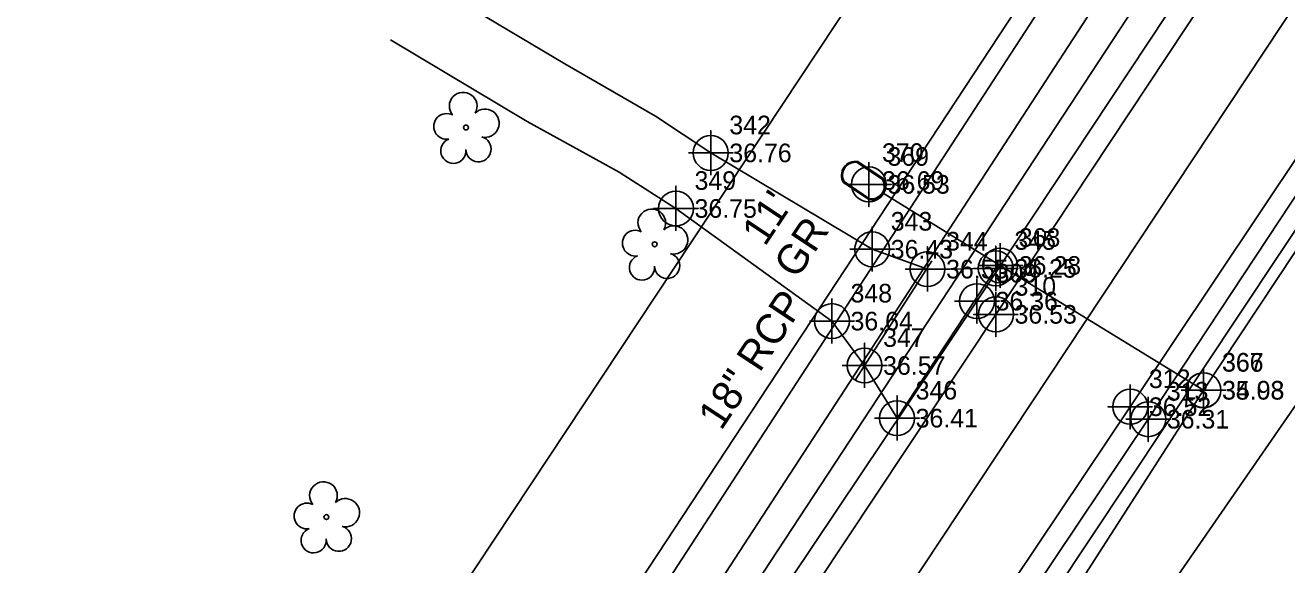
# Model space of a CAD drawing. Extents: x 2603627 to 2605187, y 896619 to 899063.
# Drawn here: x 2604617.7 to 2604787, y 898454.7 to 898527.2 of the extents above; entities that cross this region are included whole.
import ezdxf

# ---------------------------------------------------------------- set-up
doc = ezdxf.new("R2010")
doc.units = 0
for name, color, linetype in [('CTL Supplemental Horizontal and Vertical CELL', 7, 'Continuous'), ('Exist Horizontal Alignment', 7, 'Continuous'), ('Exist Horizontal Baseline Alignment', 7, 'Continuous'), ('Exist Right of Way Line', 7, 'Continuous'), ('Exist Roads EOP', 7, 'Continuous'), ('Exist Roads EOP Cogo Elevation', 7, 'Continuous'), ('Exist Roads EOP Cogo Number', 7, 'Continuous'), ('Exist Roads EOP Cogo Point CELL', 7, 'Continuous'), ('Exist Roads EOT', 7, 'Continuous'), ('Exist Roads EOT Cogo Elevation', 7, 'Continuous'), ('Exist Roads EOT Cogo Number', 7, 'Continuous'), ('Exist Roads EOT Cogo Point CELL', 7, 'Continuous'), ('Exist Roads Soil', 7, 'Continuous'), ('Exist Roads Soil Cogo Elevation', 7, 'Continuous'), ('Exist Roads Soil Cogo Number', 7, 'Continuous'), ('Exist Roads Soil Cogo Point CELL', 7, 'Continuous'), ('Exist Roads Soil Text', 7, 'Continuous'), ('Exist Structure Minor Pipes RCP 18 Inch', 7, 'Continuous'), ('Exist Structure Minor Pipes RCP 18 Inch Text', 7, 'Continuous'), ('Exist Utilities Telephone UG Cable SUE LOS C', 7, 'Continuous'), ('Exist Utilities Telephone UG FO SUE LOS C', 7, 'Continuous'), ('Exist Utilities Water Meter CELL', 7, 'Continuous'), ('Exist Utilities Water Meter Cogo Elevation', 7, 'Continuous'), ('Exist Utilities Water Meter Cogo Number', 7, 'Continuous'), ('Exist Utilities Water UG Line SUE LOS B', 7, 'Continuous'), ('Exist Utilities Water UG Line SUE LOS B Cogo Elevation', 7, 'Continuous'), ('Exist Utilities Water UG Line SUE LOS B Cogo Number', 7, 'Continuous'), ('Exist Utilities Water UG Line SUE LOS B Cogo Point CELL', 7, 'Continuous'), ('Exist Vegetation Tree CELL', 7, 'Continuous')]:
    doc.layers.add(name, color=color, linetype=linetype)

# ---------------------------------------------------------------- blocks, each defined once
blk = doc.blocks.new('EXIST ROADS EOP COGO POINT')
at = {"layer": 'Exist Roads EOP Cogo Point CELL'}
blk.add_lwpolyline([(0, 0.06), (0, -0.06), (0, 0), (0.06, 0), (-0.06, 0)], dxfattribs=at)
blk.add_circle((0, 0), 0.0469, dxfattribs=at)
blk = doc.blocks.new('EXIST ROADS EOT COGO POINT')
at = {"layer": 'Exist Roads EOT Cogo Point CELL'}
blk.add_lwpolyline([(0, 0.06), (0, -0.06), (0, 0), (-0.06, 0), (0.06, 0)], dxfattribs=at)
blk.add_circle((0, 0), 0.0469, dxfattribs=at)
blk = doc.blocks.new('EXIST ROADS SOIL COGO POINT')
at = {"layer": 'Exist Roads Soil Cogo Point CELL'}
blk.add_lwpolyline([(0, -0.06), (0, 0.06), (0, 0), (0.06, 0), (-0.06, 0)], dxfattribs=at)
blk.add_circle((0, 0), 0.0469, dxfattribs=at)
blk = doc.blocks.new('EXIST UTILITIES WATER UG LINE SUE LOS B COGO POINT')
at = {"layer": 'Exist Utilities Water UG Line SUE LOS B Cogo Point CELL'}
blk.add_lwpolyline([(0, 0.06), (0, -0.06), (0, 0), (0.06, 0), (-0.06, 0)], dxfattribs=at)
blk.add_circle((0, 0), 0.0469, dxfattribs=at)
blk = doc.blocks.new('EXIST UTILITIES WATER METER')
at = {"layer": 'Exist Utilities Water Meter CELL'}
blk.add_line((0, 0), (0, 0), dxfattribs=at)
for points in [[(-0.0408, 0.034), (0.0408, 0.034)], [(-0.0408, 0.0312), (0.0408, 0.0312)], [(0.0408, -0.0312), (-0.0413, -0.0312)], [(0.0408, -0.034), (-0.0413, -0.034)]]:
    blk.add_lwpolyline(points, dxfattribs=at)
for centre, radius, start, end in [((-0.0261, -0.0001), 0.0371, 113.178, 245.9794), ((0.0259, 0), 0.0371, 293.6483, 66.3084), ((-0.0259, -0.0001), 0.0347, 115.3009, 243.7824), ((0.0261, 0), 0.0345, 295.1272, 64.8728)]:
    blk.add_arc(centre, radius, start, end, dxfattribs=at)
blk = doc.blocks.new('CTL SUPPLEMENTAL HORIZONTAL AND VERTICAL')
at = {"layer": 'CTL Supplemental Horizontal and Vertical CELL'}
blk.add_line((0, 0), (0, 0), dxfattribs=at)
blk.add_lwpolyline([(-0.1043, 0.0004), (0.0005, 0.1052), (0.1055, 0.0002), (0.0007, -0.1047)], close=True, dxfattribs=at)

msp = doc.modelspace()

# ---------------------------------------------------------------- linework, layer by layer
at = {"layer": 'Exist Horizontal Alignment'}
msp.add_line((2604681.44, 898368.79), (2605041.11, 898911.74), dxfattribs=at)
at = {"layer": 'Exist Horizontal Baseline Alignment'}
msp.add_line((2604544.96, 898124.44), (2604793.6, 898483.9), dxfattribs=at)
at = {"layer": 'Exist Right of Way Line'}
msp.add_line((2604639.76, 898396.41), (2604999.42, 898939.36), dxfattribs=at)
at = {"layer": 'Exist Roads EOP'}
for points in [[(2604577.96, 898237.27), (2604606.45, 898281.24), (2604633.89, 898322.5), (2604662.45, 898365.47), (2604690.62, 898408.06), (2604717.29, 898448.09), (2604745.46, 898490.11), (2604773.6, 898532.6), (2604800.88, 898573.95), (2604828.34, 898615.46), (2604855.1, 898656.15), (2604883.53, 898699.09), (2604911.29, 898740.95), (2604939.38, 898783.41), (2604966.33, 898824.04), (2604993.38, 898865.27), (2605022.2, 898908.38), (2605029.46, 898919.46)], [(2604713.86, 898392.44), (2604740.28, 898432.25), (2604768.45, 898474.26), (2604797.27, 898517.92), (2604823.93, 898558.47), (2604851.31, 898599.84), (2604878.52, 898641.09), (2604906.84, 898683.65), (2604934.68, 898725.71), (2604962.63, 898767.92), (2604989.32, 898808.49), (2605016.42, 898849.59), (2605045.34, 898893.33), (2605052.55, 898904.16)]]:
    msp.add_lwpolyline(points, dxfattribs=at)
at = {"layer": 'Exist Roads EOT'}
for points in [[(2604580.65, 898235.67), (2604609.23, 898279.3), (2604636.66, 898320.72), (2604665.18, 898363.91), (2604693.37, 898406.36), (2604719.95, 898446.05), (2604748, 898488.34), (2604776.15, 898530.84), (2604803.5, 898572.3), (2604830.95, 898613.91), (2604857.58, 898654.47), (2604886.02, 898697.38), (2604913.86, 898739.33), (2604942.03, 898781.72), (2604969.06, 898822.38), (2604996.07, 898863.44), (2605024.73, 898906.73), (2605032, 898917.78)], [(2604598.04, 898223.4), (2604627.23, 898267.23), (2604654.64, 898308.57), (2604683.28, 898352.01), (2604711.27, 898394.14), (2604737.98, 898434.05), (2604766.04, 898475.94), (2604794.96, 898519.26), (2604821.61, 898559.82), (2604848.89, 898601.4), (2604876.12, 898642.73), (2604904.4, 898685.35), (2604932.33, 898727.23), (2604960.29, 898769.49), (2604987.32, 898810.19), (2605014.12, 898850.95), (2605043.08, 898894.89), (2605050.2, 898905.72)]]:
    msp.add_lwpolyline(points, dxfattribs=at)
at = {"layer": 'Exist Roads Soil'}
for p, q in [((2604709.71, 898510.01), (2604702.3, 898514.93)), ((2604705.04, 898502.55), (2604697.44, 898507.43))]:
    msp.add_line(p, q, dxfattribs=at)
for points in [[(2604702.3, 898514.93), (2604690.11, 898521.97), (2604671.82, 898532.91)], [(2604697.44, 898507.43), (2604685.07, 898514.22), (2604666.71, 898525.2)], [(2604709.71, 898510.01), (2604731.38, 898497.08), (2604738.81, 898494.41), (2604747.98, 898494.51), (2604734.72, 898474.4), (2604730.36, 898481.47), (2604725.98, 898487.43), (2604705.04, 898502.55)]]:
    msp.add_lwpolyline(points, dxfattribs=at)
at = {"layer": 'Exist Structure Minor Pipes RCP 18 Inch'}
msp.add_line((2604729.12, 898479.5), (2604739.41, 898495.51), dxfattribs=at)
at = {"layer": 'Exist Utilities Telephone UG Cable SUE LOS C'}
for p, q in [((2604658.71, 898389.49), (2604852.96, 898684.66)), ((2604753.32, 898447.21), (2604850.74, 898593.69)), ((2604580.04, 898245.37), (2604795.48, 898573.63))]:
    msp.add_line(p, q, dxfattribs=at)
at = {"layer": 'Exist Utilities Telephone UG FO SUE LOS C'}
for p, q in [((2604671.2, 898402.26), (2605014.35, 898929.48)), ((2604676.14, 898398.98), (2605019.3, 898926.2))]:
    msp.add_line(p, q, dxfattribs=at)
at = {"layer": 'Exist Utilities Water UG Line SUE LOS B'}
for points in [[(2604590.41, 898183.07), (2604608.13, 898210.78), (2604631.33, 898247.72), (2604631.98, 898248.77), (2604637.93, 898260.9), (2604650.01, 898281.75), (2604670.13, 898312.66), (2604706.14, 898370.49), (2604744.2, 898428.79), (2604775.85, 898478.14), (2604817.62, 898541.22), (2604844.76, 898580.18), (2604876.2, 898627.22), (2604907.55, 898675.15), (2604931.69, 898711.47), (2604963.51, 898758.63), (2604991.08, 898800.9), (2605022.23, 898847.26), (2605044.13, 898880.13), (2605057.71, 898900.74)], [(2604775.86, 898478.17), (2604748.57, 898494.9), (2604732.86, 898504.6)]]:
    msp.add_lwpolyline(points, dxfattribs=at)
at = {"layer": 'Exist Vegetation Tree CELL'}
for p, q in [((2604676.86, 898513.42), (2604676.86, 898513.42)), ((2604702.18, 898497.75), (2604702.18, 898497.75)), ((2604658.11, 898461.12), (2604658.11, 898461.12))]:
    msp.add_line(p, q, dxfattribs=at)
for centre in [(2604676.86, 898513.42), (2604702.18, 898497.75), (2604658.11, 898461.12)]:
    msp.add_circle(centre, 0.326, dxfattribs=at)
for centre, radius, start, end in [((2604676.48, 898516.29), 1.86, 330.1651, 219.7134), ((2604674.26, 898513.57), 1.73, 62.6636, 279.3457), ((2604679.41, 898514), 1.9, 257.1011, 134.1999), ((2604675.16, 898510.29), 1.69, 111.5671, 6.231), ((2604678.53, 898510.52), 1.7, 181.2822, 74.56), ((2604701.8, 898500.62), 1.86, 330.1651, 219.7134), ((2604699.58, 898497.9), 1.73, 62.6636, 279.3457), ((2604704.73, 898498.33), 1.9, 257.1011, 134.1999), ((2604703.86, 898494.85), 1.7, 181.2822, 74.56), ((2604700.48, 898494.62), 1.69, 111.5671, 6.231), ((2604657.72, 898463.99), 1.86, 330.1651, 219.7134), ((2604655.5, 898461.27), 1.73, 62.6636, 279.3457), ((2604660.66, 898461.71), 1.9, 257.1011, 134.1999), ((2604656.4, 898458), 1.69, 111.5671, 6.231), ((2604659.78, 898458.22), 1.7, 181.2822, 74.56)]:
    msp.add_arc(centre, radius, start, end, dxfattribs=at)

# ---------------------------------------------------------------- block references
at = {"layer": 'CTL Supplemental Horizontal and Vertical CELL', "xscale": 50, "yscale": 49.99999999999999, "rotation": 57.44453205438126}
msp.add_blockref('CTL SUPPLEMENTAL HORIZONTAL AND VERTICAL', (2604793.6, 898483.9), dxfattribs=at)
at = {"layer": 'Exist Roads EOP Cogo Point CELL', "xscale": 50, "yscale": 50}
for p in [(2604745.46, 898490.11), (2604768.45, 898474.26)]:
    msp.add_blockref('EXIST ROADS EOP COGO POINT', p, dxfattribs=at)
at = {"layer": 'Exist Roads EOT Cogo Point CELL', "xscale": 50, "yscale": 50}
for p in [(2604748, 898488.34), (2604766.04, 898475.94)]:
    msp.add_blockref('EXIST ROADS EOT COGO POINT', p, dxfattribs=at)
at = {"layer": 'Exist Roads Soil Cogo Point CELL', "xscale": 50, "yscale": 50}
for p in [(2604709.71, 898510.01), (2604705.04, 898502.55), (2604731.38, 898497.08), (2604738.81, 898494.41), (2604747.98, 898494.51), (2604725.98, 898487.43), (2604730.36, 898481.47), (2604734.72, 898474.4)]:
    msp.add_blockref('EXIST ROADS SOIL COGO POINT', p, dxfattribs=at)
at = {"layer": 'Exist Utilities Water Meter CELL', "xscale": 50, "yscale": 50, "rotation": -33.955010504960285}
msp.add_blockref('EXIST UTILITIES WATER METER', (2604730.21, 898506.3), dxfattribs=at)
at = {"layer": 'Exist Utilities Water UG Line SUE LOS B Cogo Point CELL', "xscale": 50, "yscale": 50}
for p in [(2604730.94, 898505.79), (2604748.57, 898494.9), (2604775.85, 898478.14), (2604775.87, 898478.16)]:
    msp.add_blockref('EXIST UTILITIES WATER UG LINE SUE LOS B COGO POINT', p, dxfattribs=at)

# ---------------------------------------------------------------- texts
at = {"layer": 'Exist Roads EOP Cogo Elevation'}
for s, p in [('36.36', (2604747.96, 898488.86)), ('36.31', (2604770.95, 898473.01))]:
    msp.add_text(s, height=2.5, dxfattribs=at).set_placement(p)
at = {"layer": 'Exist Roads EOP Cogo Number'}
for s, p in [('309', (2604747.96, 898492.61)), ('313', (2604770.95, 898476.76))]:
    msp.add_text(s, height=2.5, dxfattribs=at).set_placement(p)
at = {"layer": 'Exist Roads EOT Cogo Elevation'}
for s, p in [('36.53', (2604750.5, 898487.09)), ('36.52', (2604768.54, 898474.69))]:
    msp.add_text(s, height=2.5, dxfattribs=at).set_placement(p)
at = {"layer": 'Exist Roads EOT Cogo Number'}
for s, p in [('310', (2604750.5, 898490.84)), ('312', (2604768.54, 898478.44))]:
    msp.add_text(s, height=2.5, dxfattribs=at).set_placement(p)
at = {"layer": 'Exist Roads Soil Cogo Elevation'}
for s, p in [('36.76', (2604712.21, 898508.76)), ('36.75', (2604707.54, 898501.3)), ('36.43', (2604733.88, 898495.83)), ('36.55', (2604741.31, 898493.16)), ('36.25', (2604750.48, 898493.26)), ('36.64', (2604728.48, 898486.18)), ('36.57', (2604732.86, 898480.22)), ('36.41', (2604737.22, 898473.15))]:
    msp.add_text(s, height=2.5, dxfattribs=at).set_placement(p)
at = {"layer": 'Exist Roads Soil Cogo Number'}
for s, p in [('342', (2604712.21, 898512.51)), ('349', (2604707.54, 898505.05)), ('343', (2604733.88, 898499.58)), ('344', (2604741.31, 898496.91)), ('345', (2604750.48, 898497.01)), ('348', (2604728.48, 898489.93)), ('347', (2604732.86, 898483.97)), ('346', (2604737.22, 898476.9))]:
    msp.add_text(s, height=2.5, dxfattribs=at).set_placement(p)
at = {"layer": 'Exist Roads Soil Text'}
for s, p in [("11' ", (2604716.98, 898497.33)), ('GR', (2604721.28, 898492.95))]:
    msp.add_text(s, height=4, rotation=56.3361, dxfattribs=at).set_placement(p)
at = {"layer": 'Exist Structure Minor Pipes RCP 18 Inch Text'}
msp.add_text('18" RCP', height=4, rotation=56.4786, dxfattribs=at).set_placement((2604711.12, 898472.62))
at = {"layer": 'Exist Utilities Water Meter Cogo Elevation'}
msp.add_text('36.69', height=2.5, dxfattribs=at).set_placement((2604732.71, 898505.05))
at = {"layer": 'Exist Utilities Water Meter Cogo Number'}
msp.add_text('370', height=2.5, dxfattribs=at).set_placement((2604732.71, 898508.8))
at = {"layer": 'Exist Utilities Water UG Line SUE LOS B Cogo Elevation'}
for s, p in [('36.53', (2604733.44, 898504.54)), ('36.28', (2604751.07, 898493.65)), ('35.03', (2604778.35, 898476.89)), ('34.98', (2604778.37, 898476.91))]:
    msp.add_text(s, height=2.5, dxfattribs=at).set_placement(p)
at = {"layer": 'Exist Utilities Water UG Line SUE LOS B Cogo Number'}
for s, p in [('369', (2604733.44, 898508.29)), ('368', (2604751.07, 898497.4)), ('366', (2604778.35, 898480.64)), ('367', (2604778.37, 898480.66))]:
    msp.add_text(s, height=2.5, dxfattribs=at).set_placement(p)

doc.saveas('drawing.dxf')
